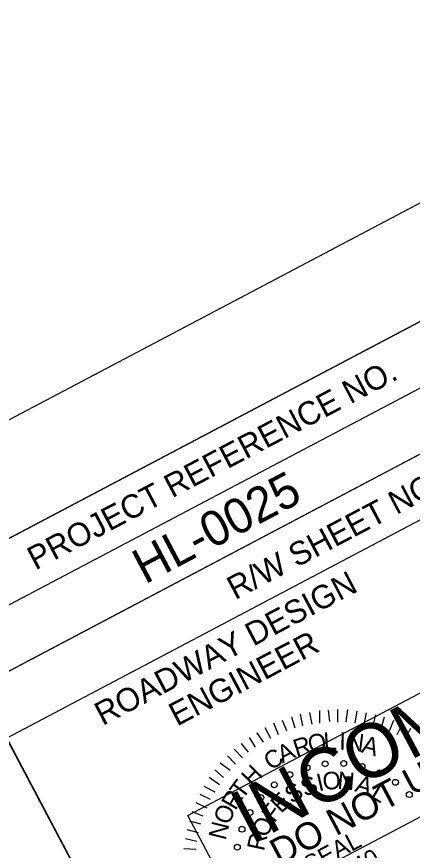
# Model space of a CAD drawing. Extents: x 1486990 to 1489232, y 497582 to 499336.
# Drawn here: x 1488377.9 to 1488462.5, y 499157.9 to 499336.3 of the extents above; entities that cross this region are included whole.
import ezdxf

# ---------------------------------------------------------------- set-up
doc = ezdxf.new("R2010")
doc.units = 0
for name, color, linetype in [('PROF-MAJR', 7, 'Continuous'), ('Prop CMT Ditch DDE', 7, 'Continuous'), ('Prop Drainage Ditch Boundaries', 7, 'Continuous'), ('Prop Drainage Structure Catch Basin Open Throat 1 CELL', 7, 'Continuous'), ('Prop Drainage Structure Drop Inlet Adjust CELL', 7, 'Continuous')]:
    doc.layers.add(name, color=color, linetype=linetype)

msp = doc.modelspace()

# ---------------------------------------------------------------- linework, layer by layer
at = {"layer": 'PROF-MAJR'}
for p, q in [((1488440.51, 499187.37), (1488441.01, 499184.92)), ((1488442.64, 499187.82), (1488442.7, 499185.13)), ((1488444.52, 499187.9), (1488444.8, 499185.45)), ((1488446.49, 499188.04), (1488446.55, 499185.35)), ((1488448.63, 499188.04), (1488448.33, 499185.39)), ((1488450.66, 499187.64), (1488450.26, 499185.17)), ((1488452.63, 499187.32), (1488452.15, 499184.81)), ((1488434.68, 499185.76), (1488435.63, 499183.55)), ((1488436.68, 499186.48), (1488437.36, 499184.12)), ((1488438.55, 499187.01), (1488439.05, 499184.56)), ((1488454.65, 499186.92), (1488454.08, 499184.58)), ((1488456.5, 499186.42), (1488455.79, 499183.9)), ((1488458.48, 499185.66), (1488457.55, 499183.36)), ((1488431.01, 499184.16), (1488432.22, 499181.86)), ((1488432.86, 499185.14), (1488433.81, 499182.7)), ((1488460.38, 499184.86), (1488459.18, 499182.64)), ((1488462.1, 499183.95), (1488460.9, 499181.74)), ((1488427.61, 499182.03), (1488428.91, 499180)), ((1488429.24, 499183), (1488430.63, 499181.02)), ((1488425.89, 499180.78), (1488427.45, 499178.89)), ((1488424.4, 499179.54), (1488426.18, 499177.66)), ((1488421.42, 499176.61), (1488423.6, 499175.05)), ((1488423, 499178.12), (1488424.74, 499176.33)), ((1488420.29, 499175.11), (1488422.16, 499173.5)), ((1488419.07, 499173.56), (1488421.26, 499172)), ((1488417.95, 499171.61), (1488420.31, 499170.37)), ((1488417.05, 499169.89), (1488419.31, 499168.83)), ((1488416.2, 499168.09), (1488418.59, 499166.98)), ((1488415.39, 499166.19), (1488417.69, 499165.26)), ((1488414.85, 499164.21), (1488417.24, 499163.55)), ((1488414.27, 499162.32), (1488416.74, 499161.7)), ((1488414.04, 499160.39), (1488416.47, 499159.86)), ((1488413.69, 499158.28), (1488416.24, 499158.16))]:
    msp.add_line(p, q, dxfattribs=at)
for centre in [(1488443.88, 499176.38), (1488447.85, 499176.46), (1488440, 499175.57), (1488451.76, 499175.81), (1488455.48, 499174.45), (1488436.33, 499174.07), (1488458.9, 499172.43), (1488433, 499171.91), (1488430.12, 499169.18), (1488461.88, 499169.81), (1488427.8, 499165.97), (1488426.1, 499162.39), (1488425.09, 499158.55)]:
    msp.add_circle(centre, 0.63, dxfattribs=at)
at = {"layer": 'Prop Drainage Ditch Boundaries'}
msp.add_lwpolyline([(1487562.23, 497581.96), (1489050.94, 498368.04), (1488539.66, 499336.34), (1487050.94, 498550.27)], close=True, dxfattribs=at)
at = {"layer": 'Prop Drainage Structure Catch Basin Open Throat 1 CELL'}
for p, q in [((1488364.06, 499204.02), (1488540.97, 499297.41)), ((1488369.93, 499192.94), (1488546.81, 499286.36)), ((1488369.93, 499192.94), (1488546.81, 499286.36))]:
    msp.add_line(p, q, dxfattribs=at)
for points in [[(1488535.14, 499308.53), (1487208.67, 498608.12), (1487698.94, 497679.61), (1489025.4, 498380.01)], [(1488358.21, 499215.12), (1488535.14, 499308.53), (1488546.81, 499286.36), (1488369.93, 499192.94)], [(1488375.76, 499181.89), (1488464.23, 499228.61), (1488516.77, 499129.11), (1488428.29, 499082.43)], [(1487698.94, 497679.61), (1487208.66, 498608.09), (1488358.21, 499215.12), (1488428.29, 499082.43), (1488605.19, 499175.82), (1489025.4, 498380.01)]]:
    msp.add_lwpolyline(points, close=True, dxfattribs=at)
at = {"layer": 'Prop Drainage Structure Drop Inlet Adjust CELL'}
msp.add_lwpolyline([(1488425.5, 499144.55), (1488414.53, 499165.33), (1488544.52, 499233.97), (1488555.49, 499213.19)], close=True, dxfattribs=at)

# ---------------------------------------------------------------- texts
at = {"layer": 'PROF-MAJR'}
for s, height, rotation, p in [('R', 3.78, 17.8566, (1488437.77, 499177.78)), ('O', 3.78, 10.9219, (1488440.57, 499178.69)), ('L', 3.78, 3.581, (1488443.64, 499179.3)), ('I', 3.78, 358.641, (1488446.86, 499179.41)), ('N', 3.78, 352.7389, (1488448.33, 499179.4)), ('A', 3.78, 344.8402, (1488451.43, 499178.89)), ('A', 3.78, 25.81, (1488434.76, 499176.41)), ('C', 3.78, 32.775, (1488432.28, 499174.88)), ('H', 3.78, 45.5784, (1488428.29, 499171.31)), ('O', 3.76, 5.71, (1488443.51, 499170.75)), ('T', 3.78, 53.2709, (1488426.21, 499168.62)), ('S', 3.76, 20.8765, (1488439.52, 499169.32)), ('I', 3.76, 13.3172, (1488442.54, 499170.46)), ('N', 3.76, 355.2281, (1488446.42, 499171.04)), ('A', 3.76, 341.7789, (1488450.05, 499170.58)), ('S', 3.76, 32.3031, (1488436.74, 499167.74)), ('L', 3.76, 329.3674, (1488453.43, 499169.31)), ('R', 3.78, 60.0105, (1488424.74, 499166.26)), ('E', 3.76, 44.424, (1488434.46, 499165.63)), ('F', 3.76, 54.235, (1488433.03, 499163.63)), ('O', 3.78, 67.7793, (1488423.33, 499163.14)), ('O', 3.76, 66.0869, (1488431.44, 499160.42)), ('N', 3.78, 75.9017, (1488422.55, 499159.91)), ('R', 3.76, 77.5829, (1488430.79, 499157.58)), ('SEAL', 3.759, 27.8351, (1488440.59, 499152.85)), ('030740', 3.759, 27.8351, (1488441.06, 499147.26))]:
    msp.add_text(s, height=height, rotation=rotation, dxfattribs=at).set_placement(p)
at = {"layer": 'Prop CMT Ditch DDE'}
msp.add_text('HL-0025', height=7.5, rotation=27.8351, dxfattribs=at).set_placement((1488405.34, 499214.76))
at = {"layer": 'Prop Drainage Structure Catch Basin Open Throat 1 CELL'}
for s, height, p in [('PROJECT REFERENCE NO.', 5.0001, (1488381.92, 499217.77)), ('R/W SHEET NO.', 5.0001, (1488424.62, 499211.43)), ('ROADWAY DESIGN', 5.0001, (1488396.3, 499184.48)), ('ENGINEER', 5, (1488412.19, 499184.35))]:
    msp.add_text(s, height=height, rotation=27.8351, dxfattribs=at).set_placement(p)
at = {"layer": 'Prop Drainage Structure Drop Inlet Adjust CELL'}
for s, height, p in [('INCOMPLETE PLANS', 11.52, (1488427.95, 499159.07)), ('DO NOT USE FOR R/W ACQUISITION', 5.76, (1488434.07, 499154.45))]:
    msp.add_text(s, height=height, rotation=27.8351, dxfattribs=at).set_placement(p)

doc.saveas('drawing.dxf')
